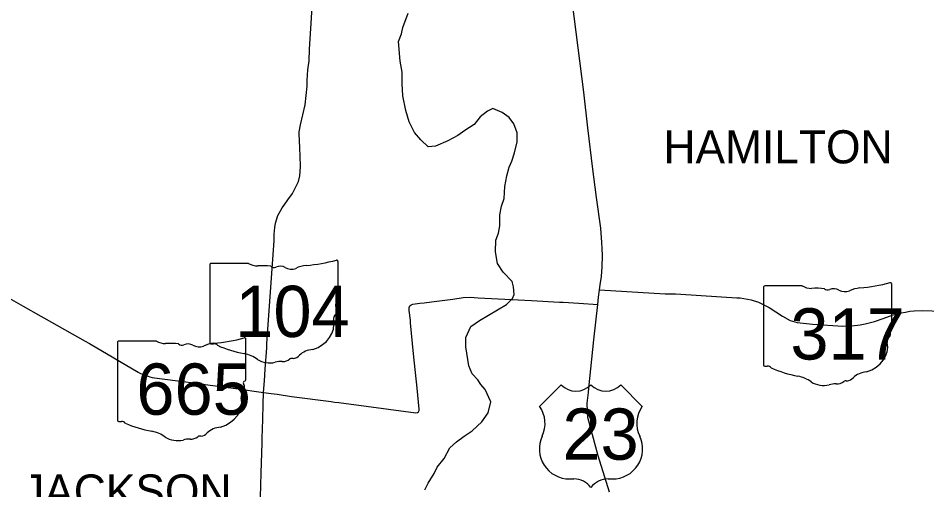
# Model space of a CAD drawing. Extents: x -1146 to -445, y -1283 to -822.
# Drawn here: x -924.4 to -862.8, y -1188.9 to -1156.9 of the extents above; entities that cross this region are included whole.
import ezdxf

# ---------------------------------------------------------------- set-up
doc = ezdxf.new("R2010")
doc.units = 0
for name, color, linetype in [('GM_X_State_Route', 7, 'Continuous'), ('GM_X_State_Shield', 7, 'Continuous'), ('GM_X_Township', 7, 'Continuous'), ('GM_X_Township_Text', 7, 'Continuous'), ('GM_X_US_Route', 7, 'Continuous'), ('GM_X_US_Shield', 7, 'Continuous')]:
    doc.layers.add(name, color=color, linetype=linetype)

msp = doc.modelspace()

# ---------------------------------------------------------------- linework, layer by layer
at = {"layer": 'GM_X_State_Route'}
for points in [[(-904.535, -1156.857), (-904.534, -1156.844), (-904.448, -1155.293), (-904.418, -1154.745), (-904.335, -1153.202)], [(-905.32, -1165.731), (-905.324, -1165.666), (-905.375, -1164.713), (-905.364, -1164.593), (-905.276, -1164.097), (-904.961, -1162.756), (-904.836, -1161.484), (-904.827, -1161.101), (-904.782, -1160.376), (-904.703, -1159.751), (-904.683, -1158.969), (-904.535, -1156.857)], [(-906.835, -1170.333), (-906.813, -1170.272), (-906.738, -1170.103), (-906.528, -1169.753), (-906.338, -1169.49), (-906.147, -1169.207), (-905.828, -1168.768), (-905.663, -1168.445), (-905.429, -1167.966), (-905.326, -1167.571), (-905.281, -1166.949), (-905.296, -1166.182), (-905.32, -1165.731)], [(-934.867, -1170.287), (-934.771, -1170.337), (-932.602, -1171.587), (-929.445, -1173.37), (-928.757, -1173.791), (-927.098, -1174.721), (-926.651, -1174.988), (-924.094, -1176.438), (-922.913, -1177.105)], [(-907.514, -1178.336), (-907.513, -1178.316), (-907.076, -1171.978), (-907.062, -1171.546), (-907.028, -1171.091), (-906.982, -1170.786), (-906.89, -1170.483), (-906.835, -1170.333)], [(-897.828, -1177.386), (-897.901, -1176.719), (-897.916, -1176.511), (-897.869, -1176.404), (-897.781, -1176.327), (-897.669, -1176.295), (-897.186, -1176.227), (-896.892, -1176.193), (-896.404, -1176.123), (-894.944, -1175.943), (-894.245, -1175.85), (-893.766, -1175.819), (-893.223, -1175.851)], [(-893.223, -1175.851), (-890.962, -1175.985), (-889.614, -1176.043), (-887.705, -1176.151), (-887.452, -1176.164), (-886.402, -1176.227), (-885.102, -1176.321)], [(-884.998, -1175.319), (-880.534, -1175.579)], [(-880.534, -1175.579), (-880.399, -1175.587)], [(-880.399, -1175.587), (-879.825, -1175.582), (-879.482, -1175.605), (-879.478, -1175.605)], [(-879.478, -1175.605), (-875.669, -1175.855)], [(-875.669, -1175.855), (-875.664, -1175.855), (-875.454, -1175.869), (-874.703, -1176.002), (-874.208, -1176.165), (-873.468, -1176.513), (-872.569, -1177.103), (-872.05, -1177.4), (-871.569, -1177.547), (-870.533, -1177.661), (-868.478, -1177.786), (-867.878, -1177.774), (-867.308, -1177.696), (-866.96, -1177.63), (-866.335, -1177.468), (-865.741, -1177.258), (-865.069, -1177.018), (-864.781, -1176.946), (-864.511, -1176.886), (-864.217, -1176.832), (-863.923, -1176.778), (-863.641, -1176.742), (-863.071, -1176.712), (-861.792, -1176.766)], [(-922.913, -1177.105), (-922.694, -1177.229)], [(-922.694, -1177.229), (-919.887, -1178.815), (-919.607, -1178.959), (-916.31, -1180.913), (-916.145, -1181.004), (-915.99, -1181.05), (-915.81, -1181.127), (-915.631, -1181.188), (-915.506, -1181.224), (-915.504, -1181.224)], [(-902.69, -1182.98), (-897.452, -1183.673), (-897.352, -1183.659), (-897.27, -1183.601), (-897.245, -1183.556), (-897.236, -1183.516), (-897.23, -1183.426), (-897.373, -1181.993), (-897.612, -1179.673), (-897.808, -1177.569), (-897.828, -1177.386)], [(-907.56, -1178.995), (-907.558, -1178.977), (-907.514, -1178.336)], [(-907.678, -1180.705), (-907.578, -1179.258)], [(-907.578, -1179.258), (-907.56, -1178.995)], [(-907.732, -1181.495), (-907.678, -1180.705)], [(-915.504, -1181.224), (-915.356, -1181.266), (-914.851, -1181.35), (-913.24, -1181.557), (-911.843, -1181.733)], [(-911.843, -1181.733), (-911.837, -1181.734), (-911.759, -1181.744), (-909.678, -1182.025), (-907.787, -1182.285)], [(-907.787, -1182.285), (-907.732, -1181.495)], [(-907.85, -1184.127), (-907.823, -1183.092), (-907.787, -1182.285)], [(-907.787, -1182.285), (-907.264, -1182.359)], [(-907.264, -1182.359), (-906.873, -1182.415)], [(-906.873, -1182.415), (-905.891, -1182.555), (-903.213, -1182.911)], [(-903.213, -1182.911), (-902.979, -1182.942), (-902.69, -1182.98)], [(-907.894, -1185.707), (-907.884, -1185.392), (-907.85, -1184.127)], [(-906.143, -1200.899), (-906.232, -1200.259), (-906.424, -1199.274), (-906.703, -1198.458), (-907.122, -1196.87), (-907.663, -1194.81), (-907.801, -1194.126), (-907.891, -1192.477), (-908.012, -1190.481), (-907.989, -1189.398), (-907.957, -1187.768), (-907.895, -1185.722), (-907.894, -1185.707)]]:
    msp.add_lwpolyline(points, dxfattribs=at)
at = {"layer": 'GM_X_State_Shield'}
for p, q in [((-902.737, -1176.154), (-902.737, -1173.39)), ((-911.438, -1173.612), (-911.438, -1178.895)), ((-908.804, -1173.521), (-911.353, -1173.521)), ((-873.862, -1175.141), (-873.862, -1180.424)), ((-871.228, -1175.05), (-873.777, -1175.05)), ((-865.161, -1177.683), (-865.161, -1174.919)), ((-902.738, -1176.153), (-902.737, -1176.154)), ((-865.162, -1177.682), (-865.161, -1177.683)), ((-917.697, -1178.892), (-917.697, -1184.175)), ((-915.063, -1178.801), (-917.611, -1178.801)), ((-908.996, -1181.434), (-908.996, -1178.67)), ((-908.997, -1181.433), (-908.996, -1181.434))]:
    msp.add_line(p, q, dxfattribs=at)
for centre, major_axis, start_param, end_param in [((-905.837, -1166.318), (9.227, 0), 4.814394, 5.042369), ((-902.834, -1173.379), (0.0969, 0), 6.141152, 7.989035), ((-911.338, -1173.601), (0.101, 0), 1.712693, 3.28349), ((-908.198, -1172.908), (0.978, 0), 4.042523, 4.731795), ((-907.873, -1176.487), (3.51, 0), 1.404758, 1.657858), ((-907.077, -1173.573), (0.282, 0), 3.836095, 5.185415), ((-906.662, -1174.184), (0.586, 0), 0.950623, 2.079405), ((-905.906, -1173.347), (0.705, 0), 4.081561, 5.145723), ((-904.66, -1175.135), (1.856, 0), 1.699011, 2.107814), ((-873.763, -1175.13), (0.101, 0), 1.712693, 3.28349), ((-870.622, -1174.437), (0.978, 0), 4.042523, 4.731795), ((-870.297, -1178.016), (3.51, 0), 1.404758, 1.657858), ((-869.501, -1175.102), (0.282, 0), 3.836095, 5.185415), ((-869.087, -1175.713), (0.586, 0), 0.950623, 2.079405), ((-867.084, -1176.664), (1.856, 0), 1.699011, 2.107814), ((-868.261, -1167.847), (9.227, 0), 4.814394, 5.042369), ((-865.258, -1174.908), (0.0969, 0), 6.141152, 7.989035), ((-868.33, -1174.876), (0.705, 0), 4.081561, 5.145723), ((-902.76, -1176.357), (0.15, 0), 1.883978, 3.671073), ((-903.713, -1176.706), (0.9, 0), 5.934695, 6.695948), ((-902.84, -1176.165), (0.104, 0), 5.05454, 6.418171), ((-902.39, -1177.311), (0.655, 0), 2.387724, 3.262537), ((-905.32, -1177.662), (2.308, 0), 5.101752, 6.440018), ((-865.265, -1177.694), (0.104, 0), 5.05454, 6.418171), ((-865.184, -1177.886), (0.15, 0), 1.883978, 3.671073), ((-866.137, -1178.235), (0.9, 0), 5.934695, 6.695948), ((-917.597, -1178.881), (0.101, 0), 1.712693, 3.28349), ((-914.457, -1178.188), (0.978, 0), 4.042523, 4.731795), ((-914.132, -1181.767), (3.51, 0), 1.404758, 1.657858), ((-912.921, -1179.464), (0.586, 0), 0.950623, 2.079405), ((-910.919, -1180.415), (1.856, 0), 1.699011, 2.107814), ((-911.338, -1178.907), (0.102, 0), 3.00124, 4.508301), ((-911.322, -1178.366), (0.776, 0), 4.665946, 4.897461), ((-911.163, -1179.2), (0.28, 0), 0.519207, 1.627899), ((-912.096, -1171.598), (9.227, 0), 4.814394, 5.042369), ((-909.093, -1178.659), (0.0969, 0), 6.141152, 7.989035), ((-867.744, -1179.191), (2.308, 0), 5.101752, 6.440018), ((-864.814, -1178.84), (0.655, 0), 2.387724, 3.262537), ((-913.335, -1178.853), (0.282, 0), 3.836095, 5.185415), ((-912.165, -1178.627), (0.705, 0), 4.081561, 5.145723), ((-907.63, -1174.453), (6.663, 0), 4.195997, 4.488961), ((-904.347, -1180.379), (1.264, 0), 1.647645, 2.488434), ((-909.617, -1181.269), (2.085, 0), 0.823519, 1.323587), ((-907.362, -1179.226), (1.323, 0), 4.026481, 4.996735), ((-906.598, -1181.053), (1.087, 0), 1.495662, 1.94098), ((-906.501, -1179.622), (0.705, 0), 4.691044, 5.507374), ((-905.863, -1180.134), (0.198, 0), 1.147584, 2.315152), ((-905.948, -1179.407), (0.746, 0), 4.937069, 5.64225), ((-873.762, -1180.436), (0.102, 0), 3.00124, 4.508301), ((-873.746, -1179.895), (0.776, 0), 4.665946, 4.897461), ((-873.587, -1180.729), (0.28, 0), 0.519207, 1.627899), ((-870.054, -1175.982), (6.663, 0), 4.195997, 4.488961), ((-909.099, -1181.445), (0.104, 0), 5.05454, 6.418171), ((-872.041, -1182.798), (2.085, 0), 0.823519, 1.323587), ((-868.372, -1180.936), (0.746, 0), 4.937069, 5.64225), ((-866.771, -1181.908), (1.264, 0), 1.647645, 2.488434), ((-909.019, -1181.637), (0.15, 0), 1.883978, 3.671073), ((-909.972, -1181.986), (0.9, 0), 5.934695, 6.695948), ((-869.786, -1180.755), (1.323, 0), 4.026481, 4.996735), ((-869.022, -1182.582), (1.087, 0), 1.495662, 1.94098), ((-868.925, -1181.151), (0.705, 0), 4.691044, 5.507374), ((-868.287, -1181.663), (0.198, 0), 1.147584, 2.315152), ((-911.579, -1182.942), (2.308, 0), 5.101752, 6.440018), ((-908.649, -1182.591), (0.655, 0), 2.387724, 3.262537), ((-917.597, -1184.187), (0.102, 0), 3.00124, 4.508301), ((-917.581, -1183.646), (0.776, 0), 4.665946, 4.897461), ((-917.422, -1184.48), (0.28, 0), 0.519207, 1.627899), ((-913.889, -1179.733), (6.663, 0), 4.195997, 4.488961), ((-915.876, -1186.549), (2.085, 0), 0.823519, 1.323587), ((-912.207, -1184.687), (0.746, 0), 4.937069, 5.64225), ((-910.606, -1185.659), (1.264, 0), 1.647645, 2.488434), ((-913.621, -1184.506), (1.323, 0), 4.026481, 4.996735), ((-912.857, -1186.333), (1.087, 0), 1.495662, 1.94098), ((-912.76, -1184.902), (0.705, 0), 4.691044, 5.507374), ((-912.122, -1185.414), (0.198, 0), 1.147584, 2.315152)]:
    msp.add_ellipse(centre, major_axis=major_axis, ratio=0.8, start_param=start_param, end_param=end_param, dxfattribs=at)
at = {"layer": 'GM_X_Township'}
msp.add_lwpolyline([(-896.851, -1188.914), (-896.622, -1188.461), (-896.214, -1187.806), (-896.007, -1187.37), (-895.523, -1186.778), (-895.143, -1186.059), (-894.695, -1185.646), (-894.171, -1185.25), (-893.632, -1184.89), (-892.977, -1184.279), (-892.558, -1183.673), (-892.36, -1182.925), (-892.755, -1182.09), (-893.054, -1181.75), (-893.257, -1181.425), (-893.624, -1181.031), (-893.868, -1180.475), (-894.068, -1179.187), (-894.072, -1178.555), (-893.713, -1177.813), (-893.138, -1177.407), (-891.302, -1176.323), (-890.962, -1175.985), (-890.907, -1175.897), (-890.781, -1175.641), (-890.82, -1175.114), (-890.924, -1174.75), (-891.531, -1174.109), (-891.906, -1173.521), (-892.06, -1172.727), (-892.027, -1171.949), (-891.845, -1171.458), (-891.753, -1170.961), (-891.746, -1170.219), (-891.649, -1169.622), (-891.472, -1169.115), (-891.409, -1168.302), (-891.291, -1167.565), (-891.114, -1166.983), (-890.947, -1166.567), (-890.769, -1166.01), (-890.581, -1165.263), (-890.578, -1164.66), (-890.799, -1164.048), (-891.115, -1163.611), (-891.603, -1163.276), (-892.22, -1162.988), (-892.586, -1163.176), (-893.095, -1163.571), (-893.504, -1164.082), (-894.128, -1164.482), (-894.617, -1164.838), (-895.282, -1165.193), (-896.127, -1165.562), (-896.609, -1165.603), (-897.111, -1165.128), (-897.537, -1164.636), (-897.902, -1163.907), (-898.131, -1163.134), (-898.335, -1162.135), (-898.386, -1161.3), (-898.376, -1160.529), (-898.528, -1159.78), (-898.632, -1158.434), (-898.439, -1157.912), (-898.329, -1157.484), (-897.985, -1156.523)], dxfattribs=at)
at = {"layer": 'GM_X_US_Route'}
for points in [[(-884.865, -1174.406), (-884.861, -1174.379), (-884.819, -1173.77), (-884.797, -1172.996), (-884.81, -1172.5), (-884.833, -1172.099), (-884.896, -1171.121), (-885.201, -1169.039), (-885.447, -1167.122), (-885.773, -1164.318), (-886.055, -1161.88), (-886.714, -1156.738), (-887.382, -1151.47), (-887.616, -1149.346), (-887.728, -1148.358), (-888.258, -1143.708), (-888.304, -1143.287)], [(-884.998, -1175.319), (-884.95, -1174.979), (-884.865, -1174.406)], [(-885.102, -1176.321), (-885.057, -1175.81), (-884.998, -1175.319)], [(-885.714, -1181.992), (-885.571, -1180.681), (-885.366, -1178.717), (-885.102, -1176.321)], [(-885.801, -1183.578), (-885.823, -1183.01), (-885.748, -1182.304), (-885.715, -1182), (-885.714, -1181.992)], [(-884.321, -1189.074), (-885.091, -1186.597), (-885.785, -1183.983), (-885.801, -1183.578)]]:
    msp.add_lwpolyline(points, dxfattribs=at)
at = {"layer": 'GM_X_US_Shield'}
for p, q in [((-887.603, -1181.783), (-889.053, -1183.234)), ((-882.092, -1183.234), (-883.542, -1181.783)), ((-887.023, -1188.164), (-886.733, -1188.164)), ((-884.413, -1188.164), (-884.123, -1188.164))]:
    msp.add_line(p, q, dxfattribs=at)
for centre, radius, start, end in [((-886.588, -1180.748), 1.45, 225.573, 314.427), ((-884.558, -1180.748), 1.45, 225.573, 314.427), ((-890.716, -1184.398), 2.03, 334.54712, 35.00093), ((-880.429, -1184.398), 2.03, 144.99907, 205.45288), ((-887.046, -1186.134), 2.03, 154.83192, 270.63826), ((-884.1, -1186.134), 2.03, 269.36174, 25.16808), ((-886.733, -1189.614), 1.45, 36.8699, 90), ((-884.413, -1189.614), 1.45, 90, 143.1301)]:
    msp.add_arc(centre, radius, start, end, dxfattribs=at)

# ---------------------------------------------------------------- texts
at = {"layer": 'GM_X_State_Shield'}
for s, p in [('104', (-909.709, -1178.523)), ('317', (-872.038, -1180.052)), ('665', (-916.421, -1183.803))]:
    msp.add_text(s, height=3.4805, dxfattribs=at).set_placement(p)
at = {"layer": 'GM_X_Township_Text'}
for s, p in [('HAMILTON', (-880.653, -1166.726)), ('JACKSON', (-924.178, -1190.113))]:
    msp.add_text(s, height=2.25, rotation=0.00001, dxfattribs=at).set_placement(p)
at = {"layer": 'GM_X_US_Shield'}
msp.add_text('23', height=3.4805, dxfattribs=at).set_placement((-887.51, -1186.859))

doc.saveas('drawing.dxf')
